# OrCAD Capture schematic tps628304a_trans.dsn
size D; title: TPS628304A; rev: 1.0; note: Datasheet: SLVSG98A     EVM: SLUUCR8; note: Synchronous Step Down Converter
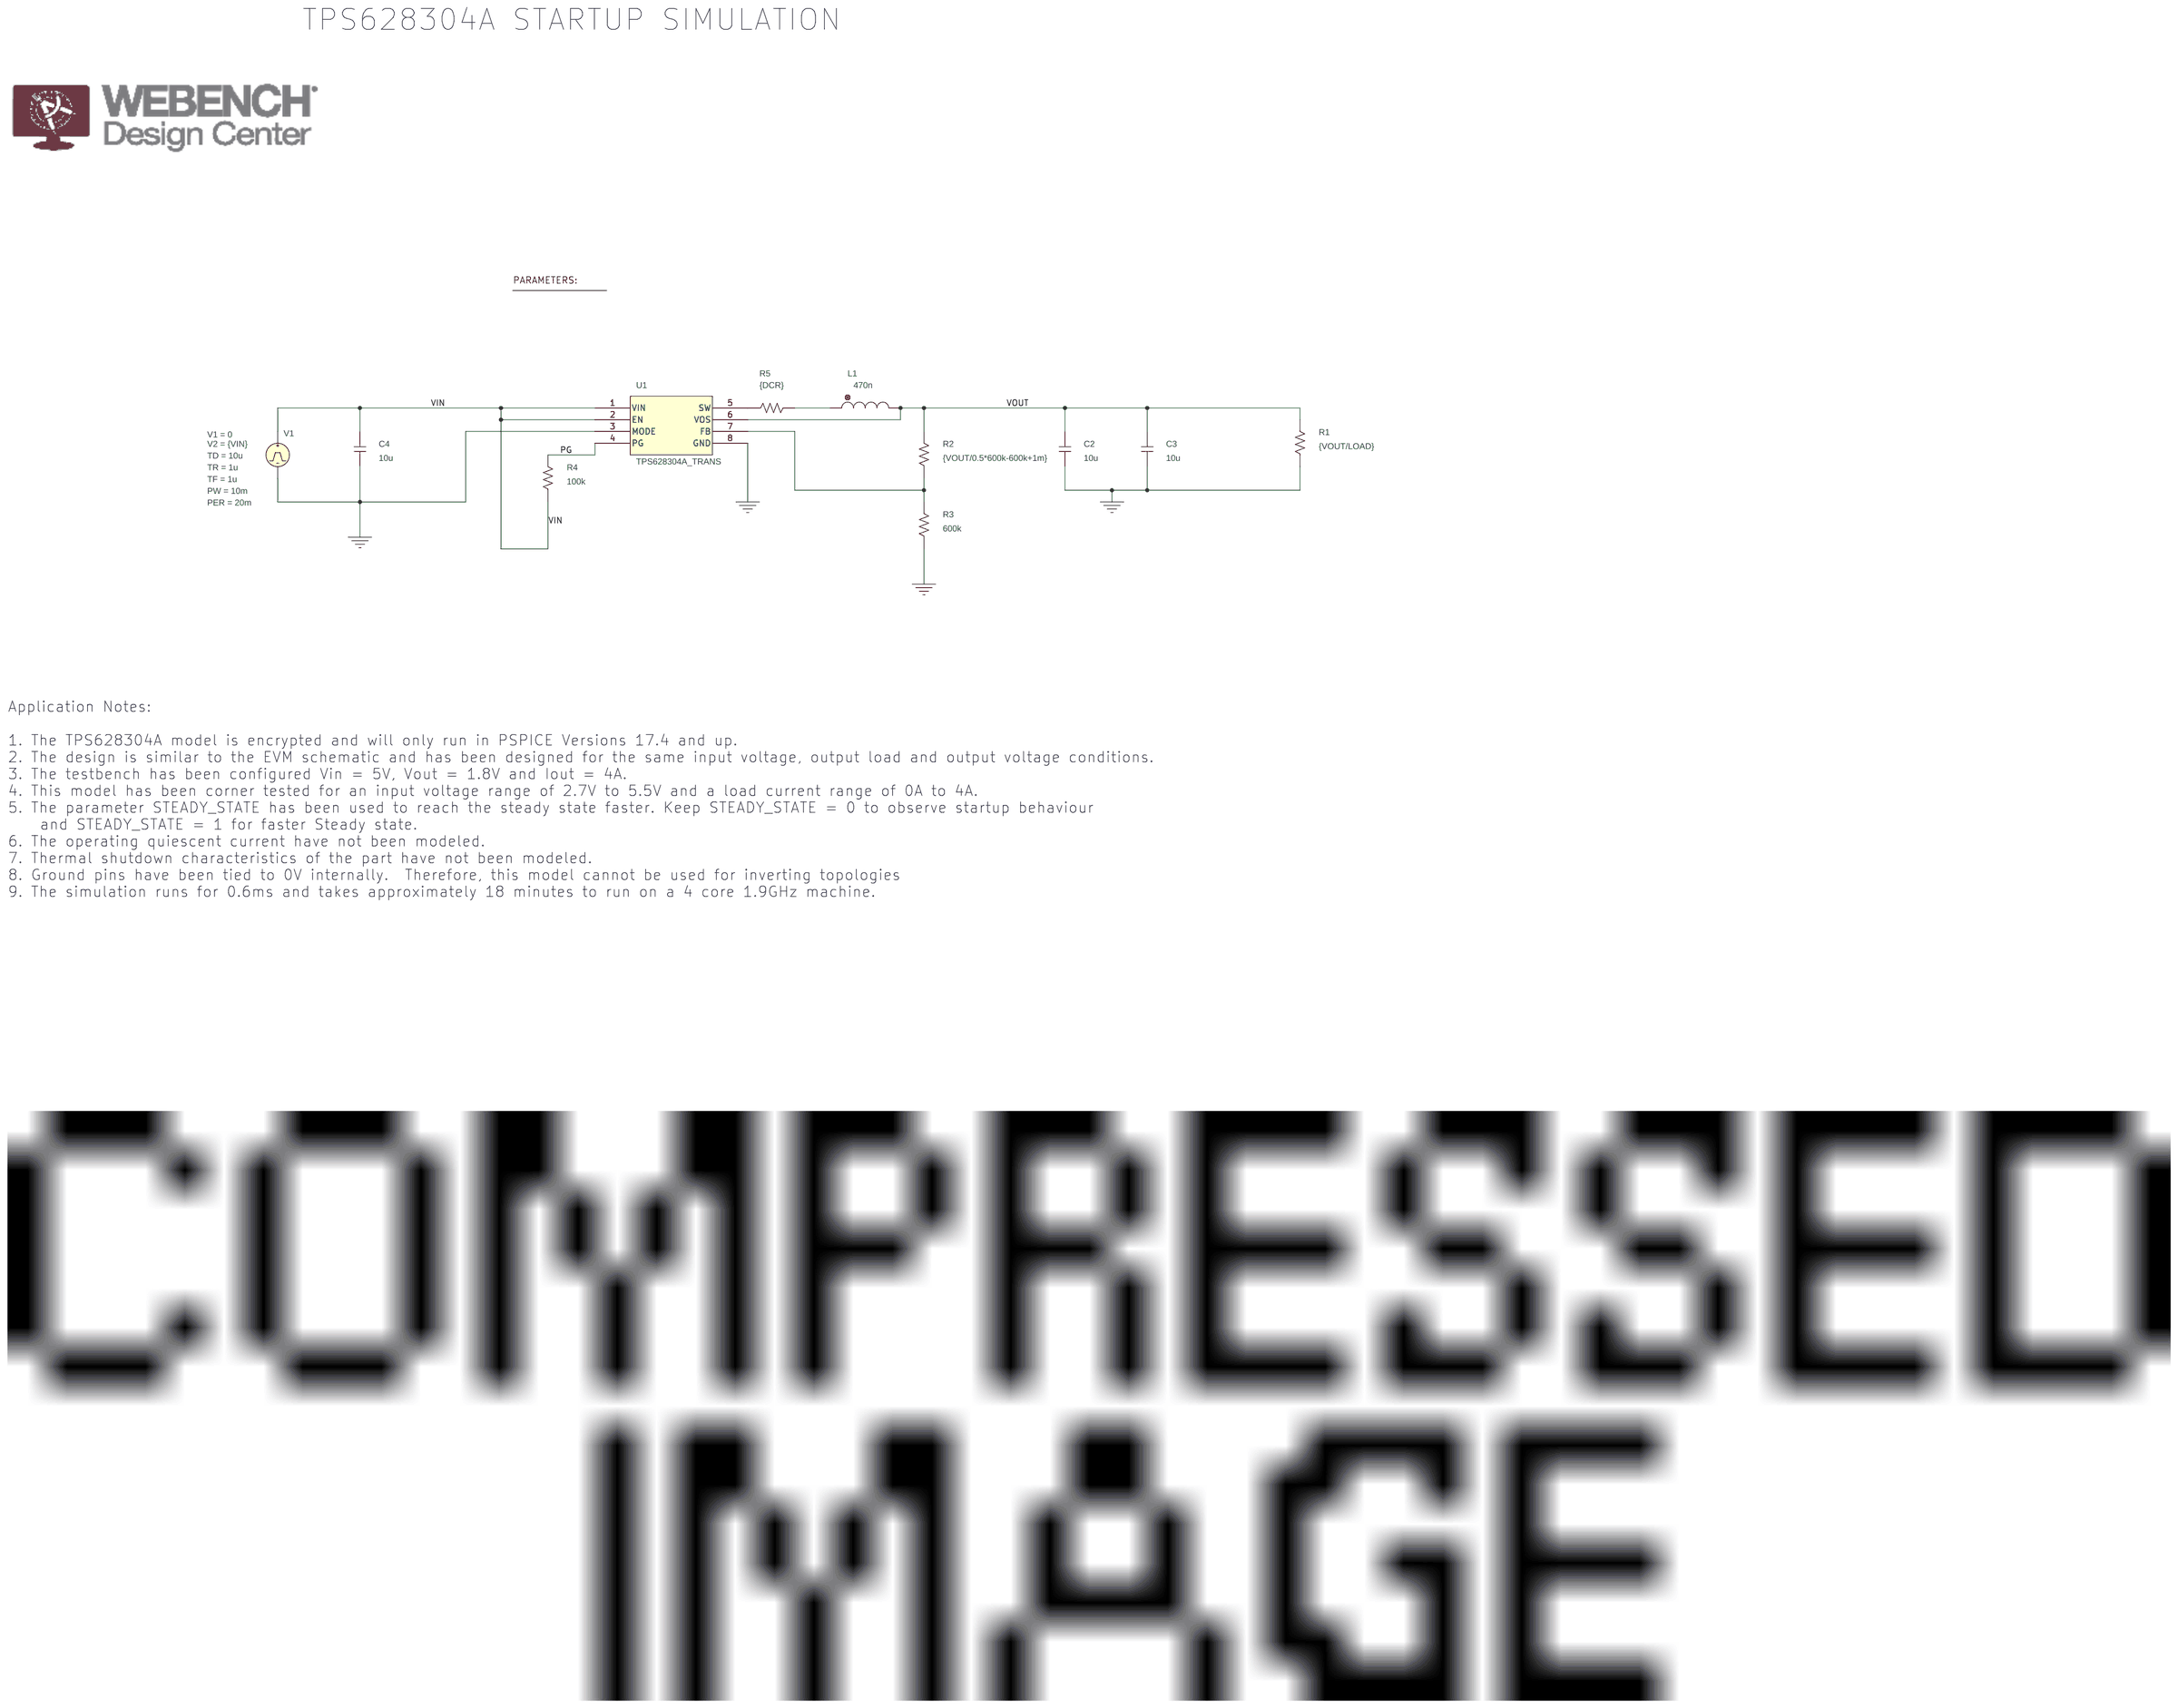
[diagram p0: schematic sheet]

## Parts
1  PARAM
C2  10u  [cap196]
C3  10u  [cap196]
C4  10u  [cap196]
L1  470n  [DISC350x175LS200x100034]
R1  {VOUT/LOAD}  [AXRC05]
R2  {VOUT/0.5*600k-600k+1m}  [AXRC05]
R3  600k  [AXRC05]
R4  100k  [AXRC05]
R5  {DCR}  [AXRC05]
U1  TPS628304A_TRANS
V1  VPULSE

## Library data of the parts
1 = PARAM: DCR: 22m; LOAD: 4; STEADY_STATE: 0; VIN: 5; VOUT: 1.8
C2-C4 = C
L1 = L_v2
R1-R5 = R
U1 = TPS628304A_TRANS
V1 = VPULSE: PER: 20m; PW: 10m; TD: 10u; TF: 1u; TR: 1u; V1: 0; V2: {VIN}

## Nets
VIN: C4.2 R4.1 U1.1(VIN) U1.2(EN) V1.1(+)
0: C2.1 C3.1 C4.1 R1.1 R3.1 U1.3(MODE) U1.8(GND) V1.2(-)
PG: R4.2 U1.4(PG)
VOUT: C2.2 C3.2 L1.2 R1.2 R2.2 U1.6(VOS)
N16774062: R2.1 R3.2 U1.7(FB)
N16777735: L1.1 R5.2
N16777806: R5.1 U1.5(SW)

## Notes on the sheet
- TPS628304A STARTUP SIMULATION
- Application Notes:
  1. The TPS628304A model is encrypted and will only run in PSPICE Versions 17.4 and up.
  2. The design is similar to the EVM schematic and has been designed for the same input voltage, output load and output voltage conditions.
  3. The testbench has been configured Vin = 5V, Vout = 1.8V and Iout = 4A.
  4. This model has been corner tested for an input voltage range of 2.7V to 5.5V and a load current range of 0A to 4A.
  5. The parameter STEADY_STATE has been used to reach the steady state faster. Keep STEADY_STATE = 0 to observe startup behaviour
      and STEADY_STATE = 1 for faster Steady state.
  6. The operating quiescent current have not been modeled.
  7. Thermal shutdown characteristics of the part have not been modeled.
  8. Ground pins have been tied to 0V internally.  Therefore, this model cannot be used for inverting topologies
  9. The simulation runs for 0.6ms and takes approximately 18 minutes to run on a 4 core 1.9GHz machine.
